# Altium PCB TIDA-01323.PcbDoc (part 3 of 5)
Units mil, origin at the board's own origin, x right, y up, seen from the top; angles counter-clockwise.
Board outline 2467 x 6135 mil, 6 copper layers (Layer 1 - Top Layer, Layer 2 - GND, Layer 3 - Sensitive, Layer 4 - GND, Layer 5 - PWR, Layer 6 - Bottom Layer), stack 62.468 mil thick; 310 components, 202 nets, 881 pads, 527 vias.
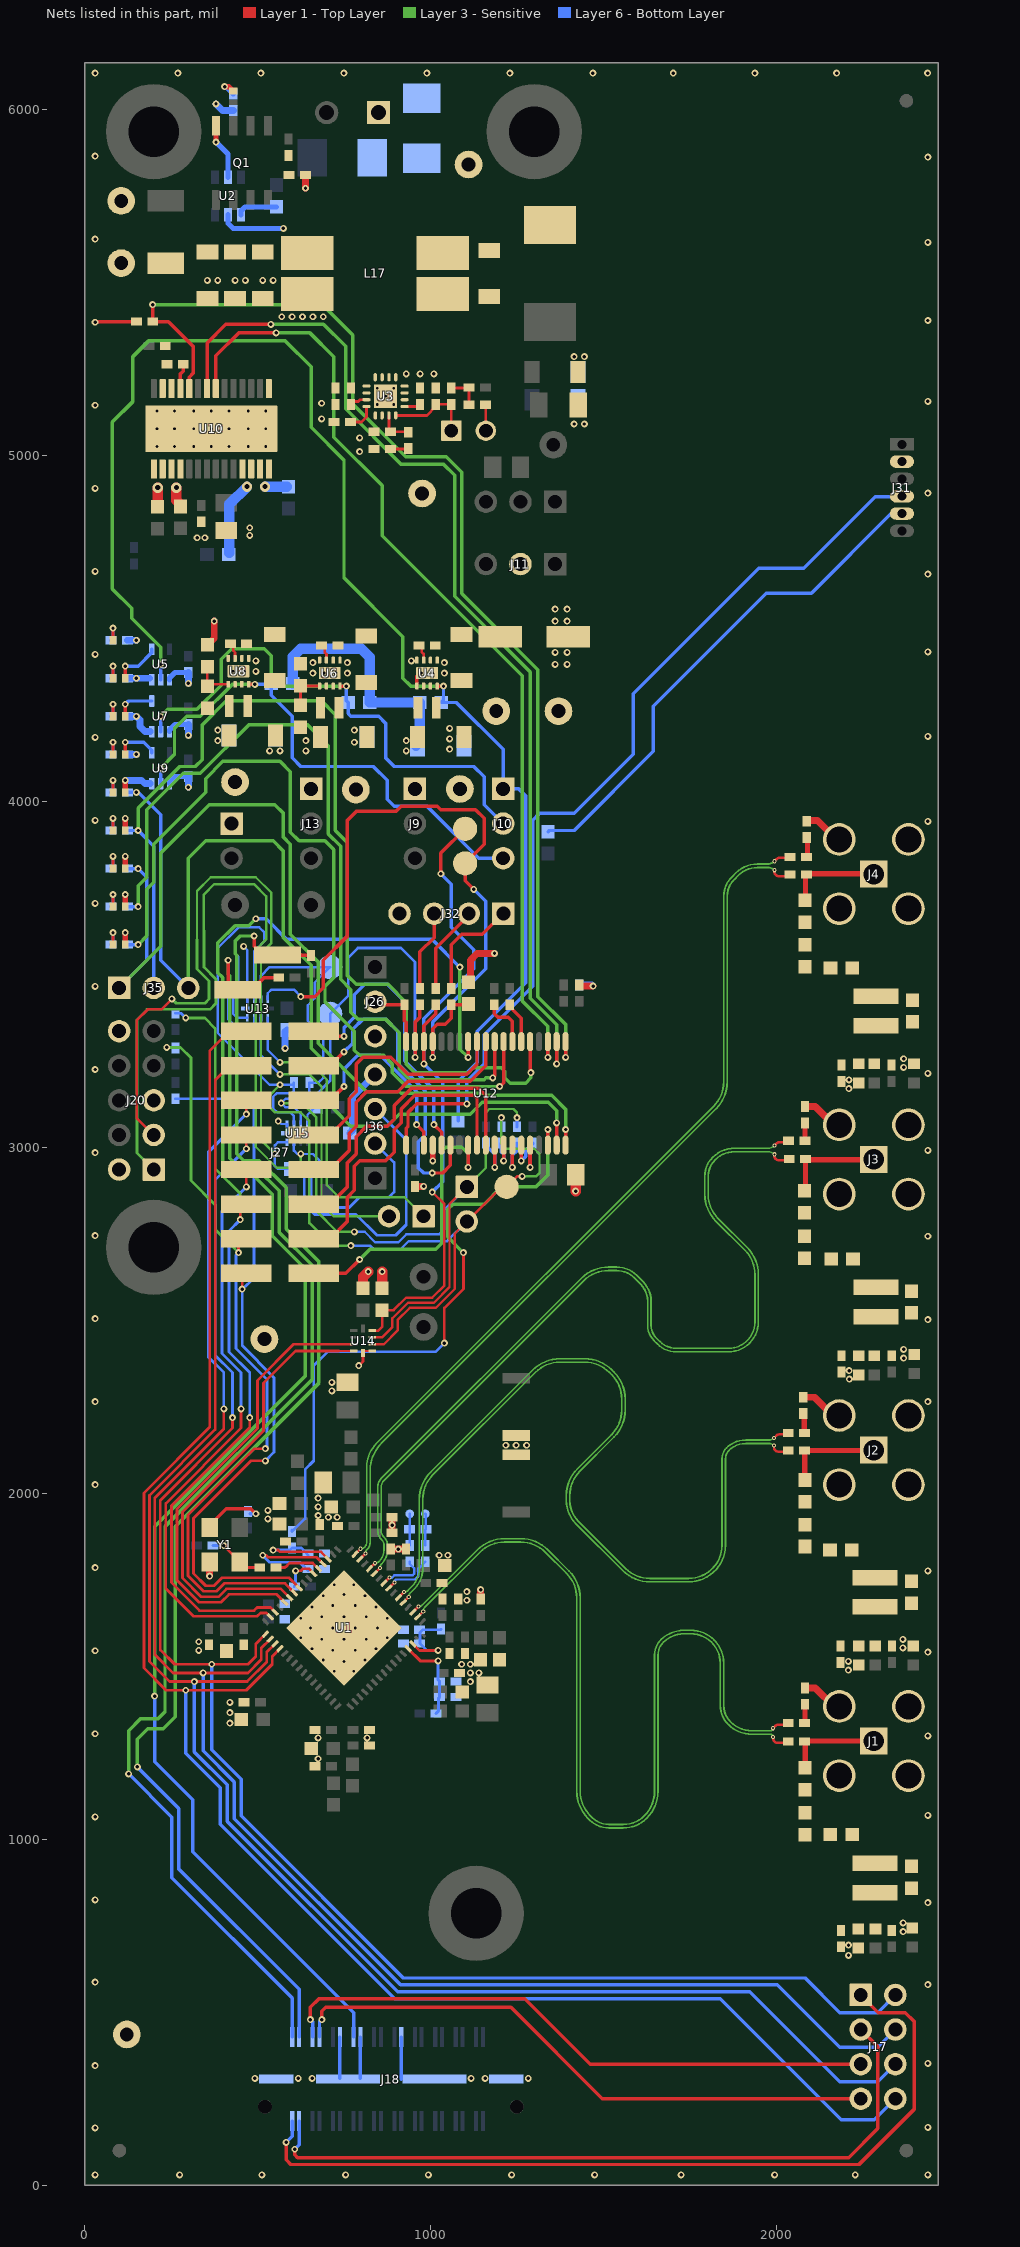
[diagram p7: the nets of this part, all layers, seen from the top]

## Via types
v1: diameter 20, hole 10, Layer 1 - Top Layer to Layer 6 - Bottom Layer, tented both sides, 397 vias
v2: diameter 19.68, hole 7.87, Layer 1 - Top Layer to Layer 6 - Bottom Layer, tented both sides, 64 vias
v3: diameter 12, hole 6, Layer 1 - Top Layer to Layer 6 - Bottom Layer, tented both sides, 58 vias
v4: diameter 30, hole 15, Layer 1 - Top Layer to Layer 6 - Bottom Layer, tented both sides, 8 vias

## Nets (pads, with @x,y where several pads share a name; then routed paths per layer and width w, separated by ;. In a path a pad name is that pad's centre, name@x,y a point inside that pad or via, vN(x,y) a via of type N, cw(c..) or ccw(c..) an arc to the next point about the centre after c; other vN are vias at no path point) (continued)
GND: C1.2 C2.2 C3.2 C4.2 C5.2 C6.2 C7.2 C8.2 C15.2 C16.2 C17.2 C18.2 C19.2 C20.2 C21.2 C22.2 C31.2 C33.2 C34.2 C35.2 C36.2 C37.2 C38.2 C39.2 C40.2 C41.2 C42.2 C43.2 C44.2 C45.2 C46.2 C47.2 C48.2 C49.2 C50.2 C51.2 C52.2 C53.2 C54.2 C55.2 C56.2 C57.2 C58.2 C59.2 C60.2 C61.2 C62.2 C63.2 C64.2 C65.2 C66.2 C67.2 C68.2 C69.2 C70.2 C71.2 C72.2 C75.2 C76.2 C77.2 C78.2 C79.2 C80.2 C81.2 C82.2 C83.2 C84.2 C85.2 C86.2 C87.2 C88.2 C89.2 C90.2 C91.2 C92.2 C93.2 C94.2 C95.2 C96.2 C97.2 C106.2 C107.2 C108.2 C109.2 C110.2 C111.2 C112.2 D3.1 D9.1 D10.1 D12.2 D13.1 D14.2 J1.MH1 J1.MH2 J1.MH3 J1.MH4 J2.MH1 J2.MH2 J2.MH3 J2.MH4 J3.MH1 J3.MH2 J3.MH3 J3.MH4 J4.MH1 J4.MH2 J4.MH3 J4.MH4 J5.1 J18.12 J18.16 J18.24 J18.MP1 J18.MP2 J18.MP3 J18.MP4 J20.2 J20.10 J26.3 J31.2 J32.4 J36.4 L17.2 R5.1 R6.1 R13.1 R14.1 R18.1 R20.1 R22.1 R25.1 R28.1 R33.2 R37.1 R38.1 R42.1 R43.1 R48.1 R51.1 R54.1 R55.1 R70.1 R71.1 R74.1 R104.1 R109.1 S1.2 S2.2 TP11.1 TP12.1 TP14.1 TP15.1 TP16.1 TP18.1 U1.65 U2.2 U3.5 U3.6 U3.10 U3.11 U3.12 U3.13 U3.14 U3.17 U4.1 U4.4 U4.5 U4.9 U5.1 U5.3 U6.1 U6.4 U6.9 U7.1 U7.3 U8.1 U8.4 U8.9 U9.1 U9.3 U10.1 U10.12 U10.13 U10.29@366,5077 U12.4 U12.15 U13.5 U13.6 U14.5 U14.6 U15.5 U15.6 Y1.2 | length 3286.9
  Layer 1 - Top Layer w7: U14.5@804.85,2411.34 U14.6@830.95,2411.34
  Layer 1 - Top Layer w8: v1(792,2369) 804.38,2381.38 U14.5@804.38,2405.44
  Layer 1 - Top Layer w10: v1@29.38,5385.87 R74.1@144.38,5386 ; U4.5@959.85,4333.47 U4.9@960,4362
  Layer 1 - Top Layer w12: v1(1287.33,2941.93) U12.15@1287.33,3006.26
  Layer 1 - Top Layer w15: D9.1@117.1,3585.87 v1(117.1,3620.87) ; D10.1@117.1,3695.87 v1(117.1,3730.87) ; D12.2@117.1,3805.87 v1(117.1,3840.87) ; D14.2@117.1,3915.87 v1(117.1,3950.87) ; D13.1@117.1,4025.87 v1(117.1,4060.87) ; v1(1005.84,2960.87) U12.4@1005.84,3006.26
  Layer 1 - Top Layer w20: R42.1@354.38,4452.37 374.38,4472.37 v1(374.38,4520.87) ; v1(361.07,1760.87) Y1.2@361.07,1800.87 ; v1(638,5772.25) C31.2@638,5810.87 ; C64.2@885,1838.87 v1(906.38,1838.87) 927.76,1838.87 C61.2@928.38,1839.49 ; C95.2@888,1885.87 888.38,1886.25 v1(888.38,1907.87) 888.38,1930.49 C92.2@888,1930.87 ; C109.2@954.38,2887.25 v1(979.38,2887.25) ; R104.1@1109.38,3477.37 1114.38,3482.37 1114.38,3540.87 1134.38,3560.87 v1(1184.38,3560.87) ; C67.2@1144.38,1694.49 v1@1144.38,1720.87 ; C111.2@1429.38,3469.49 1433,3465.87 v1(1469.38,3465.87) ; R6.1@2079.56,2277.62 2109.09,2277.62 J2.MH1@2164.28,2222.43 ; R5.1@2082,1437.62 2111.53,1437.62 J1.MH1@2166.72,1382.43 ; R13.1@2082,3117.62 2111.53,3117.62 J3.MH1@2166.72,3062.43 ; R14.1@2089,3944.62 2118.53,3944.62 J4.MH1@2173.72,3889.43
  Layer 1 - Top Layer w30: C110.2@804.38,2592.37 804.38,2625.87 v1(819.38,2640.87) ; R109.1@859.38,2592.37 v1(859.38,2640.87) ; v1(1418.88,2873.37) 1418.88,2920.37 C108.2@1419.38,2920.87
  Layer 6 - Bottom Layer w7: v1(459.38,3580.87) 469.85,3570.4 U13.6@469.85,3427.44 469.85,3400.87 U13.5@463.95,3400.87 ; v1(559.38,3075.87) 567.8,3067.44 U15.6@584.85,3067.44 U15.5@584.85,3041.34
  Layer 6 - Bottom Layer w10: J18.MP2@737.58,309.58 J18.12@737.58,428.52 ; J18.MP2@796.64,309 J18.16@796.64,428.52 ; 914.75,306.25 J18.24@914.75,428.52
  Layer 6 - Bottom Layer w15: U9.1@244.97,4051.58 244.97,4056.46 260.76,4072.25 C55.2@299.38,4072.25 ; U7.1@244.97,4201.58 244.97,4206.46 260.76,4222.25 C51.2@299.38,4222.25 ; U5.1@244.97,4351.58 244.97,4356.46 260.76,4372.25 C47.2@299.38,4372.25 ; U2.2@413.93,5695.87 413.93,5671.07 429,5656 v1(574,5656)
  Layer 6 - Bottom Layer w20: v1(117.1,4060.87) 164.38,4060.87 173.67,4051.58 U9.3@189.38,4051.58 ; R43.1@123,4135.87 v1(149.38,4135.87) ; R38.1@123,4245.87 v1(149.38,4245.87) 159.38,4235.87 159.38,4215.87 173.67,4201.58 U7.3@189.38,4201.58 ; R33.2@123,4355.87 v1(149.38,4355.87) U5.3@187.38,4355.87 ; R22.1@123,4465.87 v1(149.38,4465.87) ; v1(299.38,4040.87) C55.2@299.38,4072.25 ; v1(299.38,4190.87) C51.2@299.38,4222.25 ; v1(299.38,4340.87) C47.2@299.38,4372.25 ; v1(379.38,6015.87) 398,5997.25 R18.1@429.38,5997.25 ; v1(579.38,3285.87) 579.38,3334.37 C106.2@584.38,3339.37 ; C112.2@765.88,3040.87 774.38,3049.37 774.38,3145.87 J36.4@839.38,3210.87 ; C107.2@1429.38,3469.49 v1@1465.76,3469.49
  other v1: 30,30 274,30 512,30 754,30 993,30 1234,30 1474,30 1724,30 1994,30 2227,30 2437,30 30,166 2437,167 492,309 617,309 657,309 1117,309 1157,309 1282,309 30,346 2437,352 2437,580 30,587 2207.62,664.13 2207.62,694.13 2365.62,733.13 2365.62,758.13 2437,817 30,825 30,1065 2437,1069 674.38,1232.87 674.38,1292.87 816.38,1292.87 2437,1299 30,1305 419.38,1335.87 419.38,1365.87 419.38,1395.87 1114.38,1455.87 1114.38,1480.87 1139.38,1480.87 2207,1489 1089.38,1505.87 1114.38,1505.87 2207,1514 2437,1541 30,1545 329.38,1545.87 2365,1553 329.38,1570.87 2365,1578 1104.38,1690.87 1104.38,1715.87 1144.38,1721.87 2437,1776 30,1785 1024.38,1820.87 1049.38,1820.87 529.38,1925.87 704.38,1930.87 729.38,1930.87 674.38,1935.87 529.38,1950.87 674.38,1960.87 674.38,1985.87 30,2025 1217,2139 1247,2139 1277,2139 30,2265 2437,2265 714.38,2295.87 714.38,2320.87 2210,2330 2209.38,2354.87 2367,2391 2367,2416 2437,2502 30,2505 2437,2743 30,2745 30,2985 2437,2991 2208.62,3169.87 2209,3195 2437,3214 30,3225 2366.62,3231.13 2366.62,3256.13 30,3465 30,3705 2437,3942 30,3945 534.38,4145.87 564.38,4145.87 1054.38,4150.87 779.38,4170.87 1054.38,4180.87 30,4185 2437,4188 779.38,4205.87 1054.38,4210.87 659.38,4370.87 759.38,4370.87 1039.38,4370.87 494.38,4375.87 1359.38,4395.87 1394.38,4395.87 659.38,4400.87 759.38,4400.87 1039.38,4400.87 494.38,4405.87 944.38,4405.87 30,4425 1359.38,4430.87 1394.38,4430.87 2437,4432 1359.38,4520.87 1394.38,4520.87 1359.38,4555.87 1394.38,4555.87 2437,4657 30,4665 325,4762 347,4762 477,4769 477,4791 2437,4891 30,4905 794.38,5010.87 794.38,5050.87 1414.38,5090.87 1444.38,5090.87 684.38,5105.87 30,5145 684.38,5150.87 2437,5156 929.38,5235.87 969.38,5235.87 1009.38,5235.87 1414.38,5285.87 1444.38,5285.87 30,5385 2437,5390 569.38,5400.87 599.38,5400.87 629.38,5400.87 659.38,5400.87 689.38,5400.87 354.38,5505.87 384.38,5505.87 434.38,5505.87 464.38,5505.87 514.38,5505.87 544.38,5505.87 2437,5616 30,5625 2437,5862 30,5865 30,6105 269,6105 509,6105 749,6105 989,6105 1229,6105 1469,6105 1701,6105 1937,6105 2173,6105 2436,6105
  other v2: 721.26,1485.87 777.5,1485.87 749.38,1513.99 688.97,1518.17 809.79,1518.17 717.09,1546.28 781.67,1546.28 656.68,1550.46 842.08,1550.46 684.79,1578.58 749.38,1578.58 813.97,1578.58 624.38,1582.75 874.38,1582.75 652.5,1610.87 717.09,1610.87 781.67,1610.87 846.26,1610.87 624.38,1638.99 874.38,1638.99 684.79,1643.16 749.38,1643.16 813.97,1643.16 656.68,1671.28 842.08,1671.28 717.09,1675.46 781.67,1675.46 688.97,1703.57 809.79,1703.57 749.38,1707.75 721.26,1735.87 777.5,1735.87 692.63,4370.87 724.13,4370.87 973.63,4370.87 1005.13,4370.87 428.63,4375.87 460.13,4375.87 208.52,5025.82 259.7,5025.82 314.82,5025.82 366,5025.82 417.18,5025.82 472.3,5025.82 523.48,5025.82 208.52,5077 259.7,5077 314.82,5077 366,5077 417.18,5077 472.3,5077 523.48,5077 208.52,5128.18 259.7,5128.18 314.82,5128.18 366,5128.18 417.18,5128.18 472.3,5128.18 523.48,5128.18 845.76,5147.25 893,5147.25 869.38,5170.87 845.76,5194.49 893,5194.49
GPIO0_DES: J27.2 R56.1 U1.9 | length 2141.6
  Layer 1 - Top Layer w8: v1(455,2590) J27.2@455,2626.93 ; J27.2@462,2630.93 J27.2@466.94,2635.87 ; v1(522,2094) 480.51,2094 314.38,1927.87 314.38,1768.12 349.63,1732.87 373.68,1732.87 396.68,1755.87 590.46,1755.87 U1.9@619.93,1726.4
  Layer 6 - Bottom Layer w8: R56.1@262,3140.38 460.62,3140.38 489,3112 489,2621 v1(455,2590) 455,2428 547,2334 547,2119 v1(522,2094)
GPIO0_UC: J27.1 U12.8 | length 865.8
  Layer 1 - Top Layer w10: J27.1@661.82,2635.87 754.38,2635.87 v1(794.38,2675.87) ; v1(1108.2,2941.93) U12.8@1108.2,3006.26
  Layer 3 - Sensitive w10: v1(794.38,2675.87) 824.38,2705.87 1014.38,2705.87 1031.38,2722.87 1031.38,2989.23 1043.02,3000.87 1089.38,3000.87 1108.2,2982.05 v1(1108.2,2941.93)
GPIO1_DES: J27.4 R57.1 U1.10 | length 2212.1
  Layer 1 - Top Layer w8: v1(444.38,2695.87) 444.38,2713.31 J27.4@466.94,2735.87 ; v1(522,2129) 490.51,2129 298.38,1936.87 298.38,1761.67 343.18,1716.87 380.3,1716.87 403.3,1739.87 578.62,1739.87 U1.10@606.01,1712.48
  Layer 3 - Sensitive w8: v1(237,3289) 277,3289 307,3259 307,2904 377,2834 377,2763.25 v1(444.38,2695.87)
  Layer 6 - Bottom Layer w8: v1(237,3289) 260.62,3289 R57.1@262,3287.62 ; v1(444.38,2695.87) 437,2688.49 437,2419 527,2329 527,2134 v1(522,2129)
GPIO1_UC: J27.3 U12.9 | length 918.9
  Layer 1 - Top Layer w10: J27.3@669.38,2735.87 709.38,2735.87 759.38,2785.87 759.38,2855.87 779.38,2875.87 779.38,2945.87 794.38,2960.87 869.38,2960.87 894.38,2985.87 894.38,3050.87 914.38,3070.87 914.38,3110.87 954.38,3150.87 1124.38,3150.87 1133.79,3141.46 U12.9@1133.79,3006.26
GPIO2_DES: J27.6 R58.1 U1.14 | length 2291.9
  Layer 1 - Top Layer w8: v1(449.38,2790.87) 449.38,2818.31 J27.6@466.94,2835.87 ; v1(477,2219) 477,2190.49 250.63,1964.12 250.63,1742.07 331.83,1660.87 489.38,1660.87 498.51,1670 537.14,1670 U1.14@550.33,1656.8
  Layer 3 - Sensitive w8: v1(292,3374) 347,3374 377,3344 377,2939 449.38,2866.62 v1(449.38,2790.87)
  Layer 6 - Bottom Layer w8: R58.1@262,3387.62 278.38,3387.62 v1(292,3374) ; v1(449.38,2790.87) 417,2758.49 417,2409 477,2349 v1(477,2219)
GPIO2_UC: J27.5 U12.10 | length 882.9
  Layer 1 - Top Layer w10: J27.5@661.82,2835.87 709.38,2835.87 759.38,2885.87 759.38,2955.87 784.38,2980.87 784.38,3030.87 814.38,3060.87 874.38,3060.87 894.38,3080.87 894.38,3120.87 944.38,3170.87 1139.38,3170.87 1159.38,3150.87 U12.10@1159.38,3006.26
GPIO3_DES: J27.8 U1.15 | length 1696.9
  Layer 1 - Top Layer w8: v1(452,2244) 452,2188.49 234.38,1970.87 234.38,1724.12 313.51,1645 498.51,1645 507.63,1654.12 525.17,1654.12 U1.15@536.41,1642.88 ; v1(466.94,2885.87) J27.8@466.94,2935.87
  Layer 6 - Bottom Layer w8: v1(452,2244) 452,2349 397,2404 397,2815.93 v1(466.94,2885.87)
GPIO3_UC: J27.7 U12.29 | length 714.2
  Layer 1 - Top Layer w10: J27.7@709.38,2935.87 764.38,2990.87 764.38,3040.87 784.38,3060.87 784.38,3130.87 814.38,3160.87 904.38,3160.87 934.38,3190.87 1114.38,3190.87 1159.38,3235.87 U12.29@1159.38,3305.48
GPIO4_DES: J17.2 J27.10 U1.17 | length 4632.1
  Layer 1 - Top Layer w8: v1(427,2219) 427,2188.49 218.51,1980 218.51,1547.49 260.13,1505.87 v1(367,1505.87) 471.93,1505.87 494.38,1528.32 494.38,1564.71 U1.17@522.47,1592.8 ; v1(466.94,2995.87) J27.10@466.94,3035.87
  Layer 6 - Bottom Layer w8: v1(427,2219) 427,2349 377,2399 377,2905.93 v1(466.94,2995.87)
  Layer 6 - Bottom Layer w10: v1(367,1505.87) 367,1258.85 452,1173.85 452,1068 921,599 2082,599 2182,499 2292,499 J17.2@2343,550
GPIO4_UC: J27.9 U12.30 | length 691.8
  Layer 1 - Top Layer w10: J27.9@709.38,3035.87 764.38,3090.87 764.38,3140.87 784.38,3160.87 784.38,3240.87 804.38,3260.87 884.38,3260.87 934.38,3210.87 1104.38,3210.87 1133.79,3240.28 U12.30@1133.79,3305.48
GPIO5_DES: J17.4 J27.12 U1.18 | length 4829.2
  Layer 1 - Top Layer w8: v1(402,2244) 402,2186.49 202.63,1987.12 202.63,1533.37 255.13,1480.87 v1(342,1480.87) 471.93,1480.87 510.25,1519.19 510.25,1552.74 U1.18@536.39,1578.88 ; v1(466.94,3095.87) J27.12@466.94,3135.87
  Layer 6 - Bottom Layer w8: v1(402,2244) 402,2349 357,2394 357,2985.93 v1(466.94,3095.87)
  Layer 6 - Bottom Layer w10: v1(342,1480.87) 342,1255.57 432,1165.57 432,1059.72 912.72,579 2002,579 2182,399 2292,399 J17.4@2343,450
GPIO5_UC: J27.11 U12.3 | length 587.4
  Layer 1 - Top Layer w10: J27.11@661.82,3135.87 709.38,3135.87 v1(749.38,3175.87) ; v1(959.38,3065.87) 980.25,3045 U12.3@980.25,3006.26
  Layer 6 - Bottom Layer w10: v1(749.38,3175.87) 749.38,3225.87 789.38,3265.87 854.38,3265.87 959.38,3160.87 v1(959.38,3065.87)
GPIO6_DES: J17.6 J27.14 U1.19 | length 5022.8
  Layer 1 - Top Layer w8: J27.14@466.94,3235.87 418.87,3235.87 377,3194 377,2184.49 186.76,1994.25 186.76,1514.24 245.13,1455.87 v1(317,1455.87) 469.38,1455.87 526.13,1512.62 526.13,1540.77 U1.19@550.31,1564.95
  Layer 6 - Bottom Layer w10: v1(317,1455.87) 317,1252.28 412,1157.28 412,1051.43 904.43,559 1922,559 2182,299 2292,299 J17.6@2343,350
GPIO6_UC: J27.13 U12.6 | length 938.8
  Layer 1 - Top Layer w10: J27.13@661.82,3235.87 709.38,3235.87 v1(749.38,3275.87) ; v1(1004.38,2925.87) 1034.38,2925.87 1057.02,2948.51 U12.6@1057.02,3006.26
  Layer 6 - Bottom Layer w10: v1(749.38,3275.87) 774.38,3300.87 774.38,3340.87 804.38,3370.87 869.38,3370.87 904.38,3335.87 904.38,3242.87 984.38,3162.87 984.38,3035.87 964.38,3015.87 964.38,2940.87 979.38,2925.87 v1(1004.38,2925.87)
GPIO7_DES: J17.8 J27.16 U1.20 | length 5233.9
  Layer 1 - Top Layer w8: J27.16@466.94,3335.87 418.87,3335.87 361.13,3278.13 361.13,2191.07 170.88,2000.82 170.88,1495.12 235.13,1430.87 v1(292,1430.87) 466.93,1430.87 542,1505.94 542,1528.8 U1.20@564.24,1551.03
  Layer 6 - Bottom Layer w10: v1(292,1430.87) 292,1249 392,1149 392,1043.15 896.15,539 1837,539 2187,189 2282,189 J17.8@2343,250
GPIO7_UC: J27.15 U12.5 | length 863.3
  Layer 1 - Top Layer w10: J27.15@661.82,3335.87 676.82,3320.87 v1(749.38,3320.87) ; v1(1009.38,3065.87) 1031.43,3043.82 U12.5@1031.43,3006.26
  Layer 6 - Bottom Layer w10: v1(749.38,3320.87) 749.38,3345.87 779.38,3375.87 779.38,3440.87 809.38,3470.87 874.38,3470.87 924.38,3420.87 924.38,3250.87 1009.38,3165.87 v1(1009.38,3065.87)
I2C_SCL_DES: U1.12 U14.3 | length 1353.2
  Layer 1 - Top Layer w7: 737,2431.03 U14.3@777.8,2431.03
  Layer 1 - Top Layer w8: U1.12@578.17,1684.64 554.82,1708 416.51,1708 393.51,1685 330.15,1685 266.51,1748.64 266.51,1955 499.32,2187.81 499.32,2326.32 604.03,2431.03 737,2431.03
I2C_SCL_EXT: J20.1 J36.2 R116.1 U15.3 | length 2859.8
  Layer 3 - Sensitive w7: 344.38,3625.87 344.38,3730.87 374.38,3760.87 489.38,3760.87 524.38,3725.87 524.38,3600.87 494.38,3570.87 494.38,3001.62 555.13,2940.87 604.38,2940.87 624.38,2960.87 v1(624.38,2980.87)
  Layer 3 - Sensitive w8: J20.1@199.38,2935.87 151,2984.25 151,3369.87 180.13,3399 362,3399 379.38,3416.38 379.38,3485.87 344.38,3520.87 344.38,3625.87
  Layer 6 - Bottom Layer w7: U15.3@604.54,3014.29 604.54,2990.71 614.38,2980.87 v1(624.38,2980.87) 659.38,2980.87 699.38,2940.87 R116.1@699.38,2937.37
  Layer 6 - Bottom Layer w8: R116.1@699.38,2937.37 665.88,2937.37 654.38,2925.87 654.38,2845.87 674.38,2825.87 764.38,2825.87 794.38,2855.87 879.38,2855.87 894.38,2870.87 894.38,2955.87 J36.2@839.38,3010.87
I2C_SCL_SOC: J18.2 J28.1 R95.1 U13.3 | length 4209.2
  Layer 1 - Top Layer w10: v1(414.38,3540.87) 414.38,3455.87 J28.1@441.9,3455.87 484.38,3455.87 519.38,3490.87 R95.1@560.76,3490.87
  Layer 3 - Sensitive w10: v1(127,1189) 127,1314 162,1349 212,1349 232,1369 232,1904 657,2329 657,2659 562,2754 562,2874 497,2939 449.38,2939 419.38,2969 419.38,3495.87 415,3500.42 414.38,3501.04 v1(414.38,3540.87)
  Layer 6 - Bottom Layer w7: v1(414.38,3540.87) 414.38,3370.87 439.38,3345.87 479.38,3345.87 489.54,3356.03 U13.3@489.54,3374.29
  Layer 6 - Bottom Layer w10: v1(127,1189) 252,1064 252,889 599.79,541.21 J18.2@599.79,428.52
I2C_SCL_UC: J29.1 R93.1 R99.1 TP26.1 U13.8 U14.8 U15.8 | length 2856.5
  Layer 1 - Top Layer w7: U14.8@830.95,2450.71 859.22,2450.71 889.38,2480.87 889.38,2505.87 934.38,2550.87 1009.38,2550.87 1054.38,2595.87 1054.38,2835.87 J29.1@1104.38,2885.87
  Layer 3 - Sensitive w7: v1(568,3128) 627.25,3128 669.38,3085.87 669.38,2815.87 729.38,2755.87 v1(779.38,2755.87) ; J29.1@1104.38,2885.87 1159.38,2940.87 1159.38,3100.87 1169.38,3110.87 1239.38,3110.87 1249.38,3100.87 v1(1249.38,3085.87)
  Layer 6 - Bottom Layer w7: U13.8@509.22,3427.44 509.22,3495.71 534.38,3520.87 TP26.1@709.38,3520.87 664.38,3475.87 664.38,3430.87 644.38,3410.87 644.38,3365.87 689.38,3320.87 689.38,3200.87 675.76,3187.25 R93.1@649.38,3187.25 649.38,3160.87 629.38,3140.87 580.87,3140.87 v1(568,3128) 580.13,3115.87 604.38,3115.87 624.22,3096.03 U15.8@624.22,3067.44 ; v1(779.38,2755.87) 809.38,2755.87 839.38,2725.87 906.49,2725.87 929.62,2749 1024.38,2749 1039.38,2764 1039.38,2820.87 J29.1@1104.38,2885.87
  Layer 6 - Bottom Layer w10: R99.1@1249.38,3059.49 v1(1249.38,3085.87)
I2C_SDA_DES: U1.11 U14.4 | length 1312.3
  Layer 1 - Top Layer w7: 733.91,2411.34 U14.4@777.8,2411.34
  Layer 1 - Top Layer w8: U1.11@592.09,1698.56 566.78,1723.87 409.93,1723.87 386.93,1700.87 336.73,1700.87 282.38,1755.22 282.38,1945.87 517,2180.49 517,2319 609.34,2411.34 733.91,2411.34
I2C_SDA_EXT: J20.3 J36.3 R114.1 U15.4 | length 2956.4
  Layer 1 - Top Layer w8: J20.3@199.38,3035.87 150,3085.25 150,3367 182,3399 222,3399 v1(252,3429)
  Layer 3 - Sensitive w7: 324.38,3600.87 324.38,3740.87 364.38,3780.87 494.38,3780.87 539.38,3735.87 539.38,3590.87 509.38,3560.87 509.38,3020.87 v1(549.38,2980.87)
  Layer 3 - Sensitive w8: v1(252,3429) 264.38,3416.62 347,3416.62 359.38,3429 359.38,3480.87 324.38,3515.87 324.38,3600.87
  Layer 6 - Bottom Layer w7: U15.4@584.85,3014.29 557.8,3014.29 549.38,3005.87 v1(549.38,2980.87) 549.38,2945.87 557.88,2937.37 R114.1@594.38,2937.37
  Layer 6 - Bottom Layer w8: R114.1@594.38,2937.37 622.88,2937.37 634.38,2925.87 634.38,2835.87 664.38,2805.87 784.38,2805.87 844.38,2745.87 898.87,2745.87 929.38,2776.38 929.38,3020.87 J36.3@839.38,3110.87
I2C_SDA_SOC: J18.4 J28.2 R96.1 U13.4 | length 4325.6
  Layer 1 - Top Layer w10: v1(489.38,3610.87) 489.38,3580.87 514.38,3555.87 J28.2@556.86,3555.87 653,3555.87 R96.1@654.38,3554.49
  Layer 3 - Sensitive w10: v1(152,1209) 152,1289 182,1319 227,1319 262,1354 262,1904 677,2319 677,2669 582,2764 582,2884 504.5,2961.5 459.5,2961.5 439.38,2981.62 439.38,3555.62 434.38,3560.62 434.38,3595.87 449.38,3610.87 v1(489.38,3610.87)
  Layer 6 - Bottom Layer w7: U13.4@469.85,3374.29 440.95,3374.29 429.38,3385.87 429.38,3430.87 444.38,3445.87 444.38,3550.87 434.38,3560.87 434.38,3595.87 449.38,3610.87 v1(489.38,3610.87)
  Layer 6 - Bottom Layer w10: v1(152,1209) 272,1089 272,914 619.47,566.53 J18.4@619.47,428.52
I2C_SDA_UC: J29.2 R94.1 R98.1 TP27.1 U13.7 U14.7 U15.7 | length 3214.5
  Layer 1 - Top Layer w7: U14.7@830.95,2431.03 864.54,2431.03 904.38,2470.87 904.38,2500.87 939.38,2535.87 1014.38,2535.87 1069.38,2590.87 1069.38,2750.87 J29.2@1104.38,2785.87 1204.38,2885.87 TP27.1@1219.38,2885.87 1249.38,2915.87 v1(1264.38,2915.87)
  Layer 3 - Sensitive w7: v1(564.38,3180.87) 529.38,3145.87 529.38,3120.87 549.38,3100.87 624.38,3100.87 649.38,3075.87 649.38,2780.87 714.38,2715.87 v1(769.38,2715.87) ; v1(1204.38,3085.87) 1204.38,3010.87 1219.38,2995.87 1299.38,2995.87 1314.38,2980.87 1314.38,2925.87 1304.38,2915.87 v1(1264.38,2915.87)
  Layer 6 - Bottom Layer w7: U13.7@489.54,3427.44 489.54,3566.03 519.38,3595.87 519.38,3620.87 504.38,3635.87 444.38,3635.87 384.38,3575.87 384.38,3330.87 534.38,3180.87 v1(564.38,3180.87) R94.1@598,3180.87 ; 604.38,3090.87 594.38,3100.87 557.13,3100.87 545,3113 545,3146.49 554.38,3155.87 597.38,3155.87 604.38,3162.87 R94.1@604.38,3187.25 ; U15.7@604.54,3067.44 604.54,3090.87 ; v1(769.38,2715.87) 824.38,2715.87 834.38,2705.87 913.36,2705.87 936.49,2729 1047.51,2729 J29.2@1104.38,2785.87 ; R98.1@1204.38,3059.49 v1(1204.38,3085.87)
I2C_SW_DES: R107.1 R109.2 TP28.1 U12.36 U14.9 | length 1973.5
  Layer 1 - Top Layer w7: U14.9@830.95,2470.4 848.91,2470.4 859.38,2480.87 R109.2@859.38,2529.37 892.88,2529.37 929.38,2565.87 1004.38,2565.87 1039.38,2600.87 1039.38,2835.87 v1(1004.38,2870.87)
  Layer 1 - Top Layer w10: v1(980.25,3241.14) U12.36@980.25,3305.48 980.25,3351.74 1014.38,3385.87 R107.1@1014.38,3412.25 ; v1(1029.38,3790.87) 1029.38,3850.87 TP28.1@1099.38,3920.87
  Layer 6 - Bottom Layer w10: v1(1004.38,2870.87) 1034.38,2900.87 1034.38,3187.01 v1(980.25,3241.14) 980.25,3371.74 1124.38,3515.87 1124.38,3570.87 1059.38,3635.87 1059.38,3760.87 v1(1029.38,3790.87)
I2C_SW_EXTERNAL: R108.1 R113.1 TP29.1 U12.37 U15.9 | length 1185.7
  Layer 1 - Top Layer w10: v1(954.65,3260.08) U12.37@954.65,3305.48 954.65,3361.15 968.88,3375.37 R108.1@968.88,3412.25
  Layer 6 - Bottom Layer w7: U15.9@643.91,3067.44 643.91,3094.4 665.38,3115.87 R113.1@667.88,3115.87
  Layer 6 - Bottom Layer w8: R113.1@667.88,3115.87 667.88,3150.87 709.38,3192.37 TP29.1@709.38,3385.87 761.88,3438.37 761.88,3548.37 789.38,3575.87 914.38,3575.87 954.65,3535.59 v1(954.65,3260.08)
I2C_SW_SOC: R104.2 R105.1 TP25.1 U12.35 U13.9 | length 2184.4
  Layer 1 - Top Layer w10: v1(624.38,3435.87) 664.38,3435.87 689.38,3460.87 689.38,3540.87 759.38,3610.87 759.38,3945.87 784.38,3970.87 899.38,3970.87 914.38,3985.87 1019.38,3985.87 1029.38,3975.87 1129.38,3975.87 1154.38,3950.87 1154.38,3875.87 TP25.1@1099.38,3820.87 1099.38,3770.87 v1(1124.38,3745.87) ; v1(1005.84,3260.08) U12.35@1005.84,3305.48 1005.84,3342.33 1019.38,3355.87 1042.02,3355.87 1059.38,3373.23 R105.1@1059.38,3412.25 1101.51,3412.25 R104.2@1109.38,3404.37
  Layer 6 - Bottom Layer w7: U13.9@528.91,3427.44 528.91,3445.4 539.38,3455.87 604.38,3455.87 v1(624.38,3435.87)
  Layer 6 - Bottom Layer w10: v1(1005.84,3260.08) 1005.84,3362.33 1159.38,3515.87 1159.38,3710.87 v1(1124.38,3745.87)
IDX: C70.1 R47.1 R48.2 U1.46 | length 236.7
  Layer 1 - Top Layer w8: U1.46@948.43,1564.94 967.49,1545.87 v1(1021.38,1545.87)
  Layer 6 - Bottom Layer w8: v1(1021.38,1545.87) 989.38,1545.87 969.38,1565.87 969.38,1597.25 978,1605.87 1028,1605.87 R47.1@1029.38,1607.25
LED_BLUE: R59.2 U12.28 | length 2431.3
  Layer 1 - Top Layer w10: v1(1179.38,3200.87) 1184.97,3206.46 U12.28@1184.97,3305.48
  Layer 3 - Sensitive w10: v1(154.38,3695.87) 154.38,3755.87 179.38,3780.87 179.38,3975.87 284.38,4080.87 334.38,4080.87 474.38,4220.87 644.38,4220.87 704.38,4160.87 704.38,3905.87 739.38,3870.87 739.38,3485.87 769.38,3455.87 769.38,3390.87 789.38,3370.87 869.38,3370.87 909.38,3330.87 909.38,3225.87 939.38,3195.87 1154.38,3195.87 1159.38,3200.87 v1(1179.38,3200.87)
  Layer 6 - Bottom Layer w10: R59.2@123,3695.87 v1(154.38,3695.87)
LED_GREEN: J35.3 R115.2 U12.18 | length 2949.2
  Layer 1 - Top Layer w10: U12.18@1364.1,3006.26 v1(1364.1,3070.59)
  Layer 3 - Sensitive w10: J35.3@299.38,3460.87 299.38,3835.87 349.38,3885.87 544.38,3885.87 574.38,3855.87 574.38,3605.87 654.38,3525.87 654.38,3285.87 719.38,3220.87 719.38,3110.87 769.38,3060.87 874.38,3060.87 909.38,3095.87 1114.38,3095.87 1149.38,3130.87 1339.38,3130.87 1364.1,3106.14 v1(1364.1,3070.59)
  Layer 6 - Bottom Layer w10: R115.2@123,4025.87 v1(149.38,4025.87) 154.38,4025.87 219.38,3960.87 219.38,3540.87 J35.3@299.38,3460.87
LED_ORANGE: J35.2 R117.2 U12.24 | length 3010.1
  Layer 1 - Top Layer w10: U12.24@1287.33,3305.48 1287.33,3217.92 v1(1289.38,3215.87)
  Layer 3 - Sensitive w10: v1(154.38,3915.87) 154.38,3980.87 274.38,4100.87 319.38,4100.87 339.38,4120.87 339.38,4220.87 409.38,4290.87 684.38,4290.87 724.38,4250.87 724.38,3915.87 759.38,3880.87 759.38,3495.87 784.38,3470.87 877.07,3470.87 929.38,3418.56 929.38,3240.87 954.38,3215.87 1109.38,3215.87 1123.51,3230 1204.38,3230 1214.38,3220 1214.38,3200.87 1229.38,3185.87 1274.38,3185.87 1289.38,3200.87 v1(1289.38,3215.87)
  Layer 6 - Bottom Layer w10: R117.2@123,3915.87 v1(154.38,3915.87) 199.38,3870.87 J35.2@199.38,3460.87
LED_PINK: R111.2 U12.27 | length 2428.9
  Layer 1 - Top Layer w10: v1(1199.38,3175.87) 1210.56,3187.05 U12.27@1210.56,3305.48
  Layer 3 - Sensitive w10: v1(154.38,3585.87) 179.38,3610.87 179.38,3745.87 199.38,3765.87 199.38,3875.87 349.38,4025.87 349.38,4065.87 399.38,4115.87 564.38,4115.87 594.38,4085.87 594.38,3910.87 619.38,3885.87 694.38,3885.87 719.38,3860.87 719.38,3490.87 694.38,3465.87 694.38,3420.87 779.38,3335.87 779.38,3280.87 794.38,3265.87 864.38,3265.87 889.38,3240.87 889.38,3215.87 929.38,3175.87 v1(1199.38,3175.87)
  Layer 6 - Bottom Layer w10: R111.2@123,3585.87 v1(154.38,3585.87)
LED_YELLOW: J35.1 R112.2 U12.19 | length 2887.8
  Layer 1 - Top Layer w10: U12.19@1389.69,3006.26 v1(1389.69,3051.66)
  Layer 3 - Sensitive w10: J35.1@99.38,3460.87 219.38,3580.87 219.38,3850.87 359.38,3990.87 549.38,3990.87 574.38,3965.87 574.38,3895.87 594.38,3875.87 594.38,3615.87 674.38,3535.87 674.38,3300.87 814.38,3160.87 909.38,3160.87 914.38,3155.87 1154.38,3155.87 1159.38,3150.87 1349.38,3150.87 1389.69,3110.55 v1(1389.69,3051.66)
  Layer 6 - Bottom Layer w10: J35.1@99.38,3460.87 179.38,3540.87 179.38,3780.87 v1(154.38,3805.87) R112.2@123,3805.87
LOCAL_1V1: C53.1 C54.1 J15.1 L20.2 R40.2 TP10.1 U8.6
  other v1: 384.38,4175.87 384.38,4205.87
LOCAL_1V8: C49.1 C50.1 J13.1 L19.2 R35.2 TP9.1 U6.6
  other v1: 639.38,4145.87 639.38,4175.87
LOCAL_3V3: C44.1 C45.1 J9.1 L18.2 R29.2 R34.1 R39.1 TP8.1 U4.6 | length 722.8
  Layer 6 - Bottom Layer w30: R39.1@601.64,4340.87 601.64,4418.13 624.38,4440.87 799.38,4440.87 824.11,4416.14 R34.1@824.11,4285.87 R29.2@967.88,4285.87 967.88,4171.3 C45.1@957.45,4160.87
  other v1: 929.38,4145.87 929.38,4175.87
LPTX_N: C74.1 U1.57 | length 138.7
  Layer 1 - Top Layer w7: U1.57@864.91,1740.32 v3(880.9,1756.3)
  Layer 6 - Bottom Layer w7: v3(880.9,1756.3) 887.84,1756.3 894.41,1762.87 947.38,1762.87 952.38,1767.87 952.38,1782.87 939.38,1795.87 C74.1@939.38,1802.32
LPTX_P: C73.1 U1.56 | length 151.9
  Layer 1 - Top Layer w7: U1.56@878.83,1726.4 v3(894.82,1742.38)
  Layer 6 - Bottom Layer w7: v3(894.82,1742.38) 894.82,1746.31 899.38,1750.87 954.38,1750.87 964.38,1760.87 964.38,1781.87 984.38,1801.87 C73.1@984.38,1802.32
MODE: C77.1 R53.1 R55.2 U1.45 | length 259.3
  Layer 1 - Top Layer w9: U1.45@934.51,1551.02 969.65,1515.87 v1(1021.38,1515.87)
  Layer 6 - Bottom Layer w9: R53.1@1015.62,1364 1022,1370.38 1022,1407.11 R55.2@1025.76,1410.87 C77.1@1025.76,1455.87 1021.38,1460.25 v1(1021.38,1515.87)
MODE_UC: J26.2 R91.1 U12.38 | length 194
  Layer 1 - Top Layer w10: J26.2@839.38,3410.87 840.76,3412.25 R91.1@923.88,3412.25 923.88,3366.37 929.06,3361.18 U12.38@929.06,3305.48
NetC1_1: C1.1 C2.1 L1.2 L4.2 R2.2
NetC5_1: C5.1 C6.1 L2.2 L6.2 R4.2
NetC9_1: C9.1 J1.1 L7.1 | length 283.4
  Layer 1 - Top Layer w15: C9.1@2080.62,1282.99 2081.63,1284 J1.1@2290.14,1284 ; L7.1@2082.62,1209 C9.1@2082.62,1282.5
NetC10_1: C10.1 J2.1 L8.1 | length 274.9
  Layer 1 - Top Layer w15: C10.1@2080.62,2124 J2.1@2282,2124 ; L8.1@2081,2045.37 C10.1@2081,2118.87
NetC11_1: C11.1 R5.2 | length 54.9
  Layer 1 - Top Layer w15: C11.1@2080.62,1336 2082,1337.38 R5.2@2082,1390.38
NetC12_1: C12.1 R6.2 | length 53
  Layer 1 - Top Layer w15: C12.1@2079.56,2177.38 R6.2@2079.56,2230.38
NetC15_1: C15.1 C16.1 L9.2 L12.2 R10.2
NetC19_1: C19.1 C20.1 L10.2 L14.2 R12.2
NetC23_1: C23.1 J3.1 L15.1 | length 290.4
  Layer 1 - Top Layer w15: L15.1@2083.56,2874.5 C23.1@2083.56,2966 ; C23.1@2085.56,2964 J3.1@2284.44,2964
NetC24_1: C24.1 J4.1 L16.1 | length 270.9
  Layer 1 - Top Layer w15: L16.1@2083.74,3714 C24.1@2083.74,3787.5 ; C24.1@2094,3791 J4.1@2291.44,3791
NetC25_1: C25.1 R13.2 | length 53
  Layer 1 - Top Layer w15: C25.1@2082,3017.38 R13.2@2082,3070.38
NetC26_1: C26.1 R14.2 | length 53
  Layer 1 - Top Layer w15: C26.1@2089,3844.38 R14.2@2089,3897.38
NetC29_2: C29.2 C31.1
NetC30_2: C30.2 U2.1 | length 117.8
  Layer 6 - Bottom Layer w15: U2.1@451.33,5695.87 451.33,5706.33 463.5,5718.5 C30.2@553.67,5718.5
NetC32_1: C32.1 D4.2 L17.4
NetC32_2: C32.2 L17.3 U3.1 U3.15 U3.16
NetC36_1: C36.1 C37.1 C38.1 C39.1 L17.1 R17.2 R21.1 TP5.1 U3.2
NetC40_1: C40.1 U3.4 | length 82.8
  Layer 1 - Top Layer w8: C40.1@768,5096.36 799.87,5096.36 814.26,5110.75 U3.4@814.26,5141.34
NetC41_1: C41.1 R23.2 U3.7 | length 101.2
  Layer 1 - Top Layer w8: U3.7@879.22,5115.75 879.22,5072.99 C41.1@883.83,5068.37 933.83,5068.37 R23.2@935.21,5067
NetC42_1: C42.1 R23.1 | length 51.9
  Layer 1 - Top Layer w8: C42.1@883.83,5018.37 933.83,5018.37 R23.1@935.21,5019.75
NetC43_1: C43.1 C46.1 C48.1 C52.1 J11.2 R31.2 R36.2 R41.2 TP7.1 U4.2 U6.2 U8.2
NetC73_2: C73.2 R50.2 TP19.1 | length 92.6
  Layer 6 - Bottom Layer w7: C73.2@984.38,1849.57 984.38,1894.32 R50.2@986,1895.95 986,1939.25 TP19.1@984.38,1940.87
NetC74_2: C74.2 R50.1 TP20.1 | length 91.3
  Layer 6 - Bottom Layer w7: C74.2@939.38,1849.57 TP20.1@939.38,1940.87
NetD1_2: D1.2 D3.2
NetD2_2: D2.2 R18.2 | length 63.9
  Layer 1 - Top Layer w15: v1(404.38,6065.87) 417.1,6065.87 D2.2@429.38,6053.59
  Layer 6 - Bottom Layer w15: v1(404.38,6065.87) 408,6065.87 R18.2@429.38,6044.49
NetD5_1: D5.1 R22.2 | length 72.4
  Layer 1 - Top Layer w10: D5.1@81.66,4465.87 v1(81.66,4500.87)
  Layer 6 - Bottom Layer w10: R22.2@75.76,4465.87 81.66,4471.77 v1(81.66,4500.87)
NetD6_1: D6.1 U5.4 | length 137.9
  Layer 1 - Top Layer w10: D6.1@117.1,4355.87 v1(117.1,4390.87)
  Layer 6 - Bottom Layer w10: v1(117.1,4390.87) 154.38,4390.87 193.79,4430.28 U5.4@193.79,4440.16
NetD6_2: D6.2 R33.1 | length 72.4
  Layer 1 - Top Layer w10: D6.2@81.66,4355.87 v1(81.66,4390.87)
  Layer 6 - Bottom Layer w10: R33.1@75.76,4355.87 81.66,4361.77 v1(81.66,4390.87)
NetD7_1: D7.1 U7.4 | length 115.5
  Layer 1 - Top Layer w10: D7.1@117.1,4245.87 v1(117.1,4280.87)
  Layer 6 - Bottom Layer w10: v1(117.1,4280.87) 126.39,4290.16 U7.4@193.79,4290.16
NetD7_2: D7.2 R38.2 | length 72.4
  Layer 1 - Top Layer w10: D7.2@81.66,4245.87 v1(81.66,4280.87)
  Layer 6 - Bottom Layer w10: R38.2@75.76,4245.87 81.66,4251.78 v1(81.66,4280.87)
NetD8_1: D8.1 R43.2 | length 72.4
  Layer 1 - Top Layer w10: D8.1@81.66,4135.87 v1(81.66,4170.87)
  Layer 6 - Bottom Layer w10: R43.2@75.76,4135.87 81.66,4141.77 v1(81.66,4170.87)
NetD8_2: D8.2 U9.4 | length 128.6
  Layer 1 - Top Layer w10: D8.2@117.1,4135.87 v1(117.1,4170.87)
  Layer 6 - Bottom Layer w10: v1(117.1,4170.87) 170.25,4170.87 193.79,4147.33 U9.4@193.79,4140.16
NetD9_2: D9.2 R111.1 | length 72.4
  Layer 1 - Top Layer w10: D9.2@81.66,3585.87 v1(81.66,3620.87)
  Layer 6 - Bottom Layer w10: R111.1@75.76,3585.87 81.66,3591.78 v1(81.66,3620.87)
NetD10_2: D10.2 R59.1 | length 72.4
  Layer 1 - Top Layer w10: D10.2@81.66,3695.87 v1(81.66,3730.87)
  Layer 6 - Bottom Layer w10: R59.1@75.76,3695.87 81.66,3701.78 v1(81.66,3730.87)
NetD12_1: D12.1 R112.1 | length 72.4
  Layer 1 - Top Layer w10: D12.1@81.66,3805.87 v1(81.66,3840.87)
  Layer 6 - Bottom Layer w10: R112.1@75.76,3805.87 81.66,3811.78 v1(81.66,3840.87)
NetD13_2: D13.2 R115.1 | length 72.4
  Layer 1 - Top Layer w10: D13.2@81.66,4025.87 v1(81.66,4060.87)
  Layer 6 - Bottom Layer w10: R115.1@75.76,4025.87 81.66,4031.77 v1(81.66,4060.87)
NetD14_1: D14.1 R117.1 | length 72.4
  Layer 1 - Top Layer w10: D14.1@81.66,3915.87 v1(81.66,3950.87)
  Layer 6 - Bottom Layer w10: R117.1@75.76,3915.87 81.66,3921.77 v1(81.66,3950.87)
NetJ8_1: J8.1 R27.1 R28.2 U3.8 | length 254.1
  Layer 1 - Top Layer w8: U3.8@898.91,5115.75 989.26,5115.75 1014.38,5140.87 R28.2@1014.38,5147.74 R27.1@1059.38,5147.74 J8.1@1059.38,5071.36
NetJ8_2: J8.2 R26.1 | length 75.6
  Layer 1 - Top Layer w8: R26.1@1158,5146.36 1159.38,5144.98 J8.2@1159.38,5071.36
NetJ17_1: J17.1 J18.1 | length 2446.1
  Layer 1 - Top Layer w10: v1(582,124) 582,74 596,60 2238,60 2397,219 2397,474 2372,499 2294,499 J17.1@2243,550
  Layer 6 - Bottom Layer w10: v1(582,124) 599.79,141.79 J18.1@599.79,185.61
NetJ17_3: J17.3 J18.3 | length 2132.2
  Layer 1 - Top Layer w10: v1(607,104) 607,88 615,80 2208,80 2292,164 2292,401 J17.3@2243,450
  Layer 6 - Bottom Layer w10: v1(607,104) 619.47,116.47 J18.3@619.47,185.61
NetJ17_5: J17.5 J18.6 | length 1768
  Layer 1 - Top Layer w10: v1(652,479) 652,514 677,539 1272,539 1461,350 J17.5@2243,350
  Layer 6 - Bottom Layer w10: v1(652,479) 658.84,472.16 J18.6@658.84,428.52
NetJ17_7: J17.7 J18.8 | length 1748.5
  Layer 1 - Top Layer w10: v1(685.37,479) 685.37,502.37 697,514 1232,514 1496,250 J17.7@2243,250
  Layer 6 - Bottom Layer w10: J18.8@678.53,428.52 678.53,472.16 v1(685.37,479)
NetJ30_1: J30.1 U13.1 | length 921.1
  Layer 3 - Sensitive w7: v1(564.38,3245.87) 649.38,3245.87 699.38,3195.87 699.38,2890.87 734.38,2855.87 924.38,2855.87 J30.1@979.38,2800.87
  Layer 6 - Bottom Layer w7: U13.1@528.91,3374.29 528.91,3281.34 v1(564.38,3245.87)
NetJ30_2: J30.2 U13.2 | length 870.3
  Layer 3 - Sensitive w7: v1(564.38,3210.87) 649.38,3210.87 684.38,3175.87 684.38,2835.87 719.38,2800.87 J30.2@879.38,2800.87
  Layer 6 - Bottom Layer w7: U13.2@509.22,3374.29 509.22,3266.03 v1(564.38,3210.87)
NetJ31_5: J31.5 R106.1 | length 1484.9
  Layer 6 - Bottom Layer w10: R106.1@1339.38,3912.37 1342.88,3915.87 1414.38,3915.87 1643.13,4144.62 1643.13,4275.13 1970.12,4602.12 2100.63,4602.12 2329.38,4830.87 J31.5@2367.38,4830.87
NetJ32_1: J32.1 R105.2 | length 314
  Layer 1 - Top Layer w10: R105.2@1059.38,3459.49 1059.38,3585.87 1089.38,3615.87 1149.38,3615.87 1209.1,3675.59 J32.1@1209.88,3675.59
NetJ32_2: J32.2 R107.2 | length 255.7
  Layer 1 - Top Layer w10: R107.2@1014.38,3459.49 1014.38,3575.87 1109.88,3671.37 J32.2@1109.88,3675.59
NetJ32_3: J32.3 R108.2 | length 233.1
  Layer 1 - Top Layer w10: R108.2@968.88,3459.49 968.88,3565.37 1009.88,3606.37 J32.3@1009.88,3675.59
NetL3_1: L3.1 L7.2
NetL3_2: L3.2 L27.1
NetL4_1: L4.1 L27.2 R2.1
NetL5_1: L5.1 L8.2
NetL5_2: L5.2 L28.1
NetL6_1: L6.1 L28.2 R4.1
NetL11_1: L11.1 L15.2
NetL11_2: L11.2 L29.1
NetL12_1: L12.1 L29.2 R10.1
NetL13_1: L13.1 L16.2
NetL13_2: L13.2 L30.1
NetL14_1: L14.1 L30.2 R12.1
NetL18_1: L18.1 U4.7
NetL19_1: L19.1 U6.7
NetL20_1: L20.1 U8.7
NetQ1_4: Q1.4 U2.5 | length 163.3
  Layer 1 - Top Layer w15: v1(379.38,5905.87) Q1.4@379.38,5953.15
  Layer 6 - Bottom Layer w15: v1(379.38,5905.87) 413.93,5871.32 U2.5@413.93,5804.13
NetR21_2: R21.2 U3.3 | length 50.6
  Layer 1 - Top Layer w8: R21.2@769.38,5147.25 778,5155.87 790.38,5155.87 795.54,5161.03 U3.3@814.26,5161.03
NetR24_2: R24.2 R26.2 R27.2 | length 101.9
  Layer 1 - Top Layer w8: R27.2@1059.38,5194.98 1109.38,5194.98 R24.2@1110.76,5196.36 R26.2@1110.76,5146.36
NetR25_2: R25.2 U3.9 | length 47.5
  Layer 1 - Top Layer w8: U3.9@924.5,5141.34 962.98,5141.34 R25.2@969.38,5147.74
NetR31_1: R31.1 U4.3 | length 48.3
  Layer 1 - Top Layer w8: R31.1@965.76,4450.87 974.38,4442.25 974.38,4430.87 979.54,4425.71 U4.3@979.54,4408.27
NetR35_1: R35.1 R37.2 U6.5 | length 111
  Layer 1 - Top Layer w8: R35.1@623.38,4277.37 623.38,4332.56 624.28,4333.47 U6.5@678.85,4333.47
NetR36_1: R36.1 U6.3 | length 48.3
  Layer 1 - Top Layer w8: R36.1@684.76,4450.87 693.38,4442.25 693.38,4430.87 698.54,4425.71 U6.3@698.54,4408.27
NetR40_1: R40.1 R42.2 U8.5 | length 120
  Layer 1 - Top Layer w8: R42.2@354.38,4389.37 R40.1@354.38,4332.37 360.48,4338.47 U8.5@414.85,4338.47
NetR41_1: R41.1 U8.3 | length 48.3
  Layer 1 - Top Layer w8: R41.1@420.76,4455.87 429.38,4447.25 429.38,4435.87 434.54,4430.71 U8.3@434.54,4413.27
NetR44_2: R44.2 Y1.1 | length 182.4
  Layer 1 - Top Layer w10: Y1.1@361.07,1900.87 361.07,1907.56 409.38,1955.87 479.38,1955.87 v1(494.38,1940.87)
  Layer 6 - Bottom Layer w10: R44.2@478.2,1940.87 v1(494.38,1940.87)
NetR45_1: R45.1 R46.2 Y1.3 | length 163.4
  Layer 1 - Top Layer w8: v1(402,1849) 402,1848.25 448.53,1801.72 Y1.3@447.69,1800.87 462.69,1785.87 R46.2@505.76,1785.87
  Layer 6 - Bottom Layer w8: R45.1@370.62,1849 v1(402,1849)
NetR46_1: R46.1 U1.5 | length 134.9
  Layer 1 - Top Layer w8: R46.1@553,1785.87 578.44,1785.87 580.32,1787.74 581.25,1787.74 592.38,1798.87 658.82,1798.87 U1.5@675.61,1782.08
NetR49_1: R49.1 R51.2 U1.3 | length 283.6
  Layer 1 - Top Layer w8: v1(544.38,1835.87) 559.38,1835.87 564.38,1830.87 682.49,1830.87 U1.3@703.45,1809.92
  Layer 6 - Bottom Layer w8: v1(544.38,1835.87) 593,1835.87 R49.1@599.38,1842.25 626,1842.25 640.76,1827.49 640.76,1825.87 R51.2@645.76,1820.87
NetR52_1: R52.1 U1.6 | length 107
  Layer 1 - Top Layer w8: v1(609.38,1775.87) 624.38,1775.87 630.38,1781.87 647.98,1781.87 U1.6@661.69,1768.16
  Layer 6 - Bottom Layer w8: R52.1@605.76,1730.87 609.38,1734.49 v1(609.38,1775.87)
NetR54_2: R54.2 U1.4 | length 335.8
  Layer 1 - Top Layer w8: v1(514.38,1820.87) 524.38,1820.87 530.25,1815 670.53,1815 U1.4@689.53,1796
  Layer 6 - Bottom Layer w8: v1(514.38,1820.87) 534.38,1800.87 621.38,1800.87 645.76,1776.49 R54.2@645.76,1775.87
NetR64_2: R64.2 U10.27 U10.28 | length 62.5
  Layer 6 - Bottom Layer w30: v4(521,4910) R64.2@583.5,4910
NetR66_2: R66.2 U10.25 U10.26 | length 212.3
  Layer 6 - Bottom Layer w30: R66.2@417.5,4719 417.5,4858.5 v4(469,4910)
NetR71_2: R71.2 U10.11 | length 73.7
  Layer 1 - Top Layer w10: U10.11@276.43,5193.14 276.43,5235.43 284.62,5243.62 R71.2@284.62,5263.49
NetR78_2: R78.2 U10.17 U10.18 | length 59.2
  Layer 1 - Top Layer w30: v4(265,4907) 265,4870 276.29,4858.71 R78.2@276.29,4852.5
NetR80_2: R80.2 U10.15 U10.16 | length 54.3
  Layer 1 - Top Layer w30: R80.2@211,4852.68 v4(211,4907)
NetR97_2: R97.2 U12.11 | length 145.2
  Layer 1 - Top Layer w10: v1(1184.97,2941.93) U12.11@1184.97,3006.26
  Layer 6 - Bottom Layer w10: R97.2@1159.38,3012.25 1159.38,3005.87 1184.97,2980.28 v1(1184.97,2941.93)
NetR98_2: R98.2 U12.12 | length 99.3
  Layer 1 - Top Layer w10: v1(1210.56,2960.87) U12.12@1210.56,3006.26
  Layer 6 - Bottom Layer w10: R98.2@1204.38,3012.25 1204.38,2985.87 1210.56,2979.69 v1(1210.56,2960.87)
NetR99_2: R99.2 U12.13 | length 140.1
  Layer 1 - Top Layer w10: v1(1236.15,2941.93) U12.13@1236.15,3006.26
  Layer 6 - Bottom Layer w10: v1(1236.15,2941.93) 1236.15,2977.64 1249.38,2990.87 R99.2@1249.38,3012.25
NetR100_2: R100.2 U12.14 | length 110.3
  Layer 1 - Top Layer w10: v1(1261.74,2960.87) U12.14@1261.74,3006.26
  Layer 6 - Bottom Layer w10: v1(1261.74,2960.87) 1274.38,2973.51 1274.38,2990.87 1294.38,3010.87 R100.2@1294.38,3012.25
NetR101_2: R101.2 U12.25 | length 120.5
  Layer 1 - Top Layer w10: R101.2@1228.62,3412.25 1228.62,3406.63 1261.74,3373.51 U12.25@1261.74,3305.48
NetR102_2: R102.2 U12.26 | length 146.1
  Layer 1 - Top Layer w10: R102.2@1183.62,3412.25 1183.62,3386.63 1194.38,3375.87 1224.38,3375.87 1236.15,3364.1 U12.26@1236.15,3305.48
NRESET_SOC: J18.14 U12.31 | length 4820.5
  Layer 1 - Top Layer w10: v1(1108.2,3260.08) U12.31@1108.2,3305.48
  Layer 3 - Sensitive w10: v1(202,1414) 202,1904 637,2339 637,2649 542,2744 542,2864 487,2919 431.25,2919 399.38,2950.87 399.38,3490.87 385,3505.25 385,3591.49 434.38,3640.87 474.38,3640.87 v1(494.38,3660.87) ; v1(1084.38,3520.87) 1084.38,3283.9 v1(1108.2,3260.08)
  Layer 6 - Bottom Layer w10: v1(202,1414) 202,1224 312,1114 312,964 776.95,499.05 J18.14@776.95,428.52 ; v1(494.38,3660.87) 524.38,3660.87 584.38,3600.87 1004.38,3600.87 v1(1084.38,3520.87)
PDB_UB960: R49.2 U12.17 | length 1849.7
  Layer 1 - Top Layer w8: v1(1039.38,2434) 1039.38,2535.87 1094.38,2590.87 v1(1094.38,2695.87)
  Layer 1 - Top Layer w10: U12.17@1338.51,3006.26 v1(1338.51,3051.66)
  Layer 3 - Sensitive w10: v1(1094.38,2695.87) 1049.38,2740.87 1049.38,2820.87 1064.38,2835.87 1154.38,2835.87 1204.38,2885.87 1304.38,2885.87 1338.51,2920 v1(1338.51,3051.66)
  Layer 6 - Bottom Layer w8: R49.2@599.38,1893.87 R49.2@599.38,1889.49 637,1927.11 637,2069 662,2094 662,2369 702,2409 1014.38,2409 v1(1039.38,2434)
PG_1V1: J10.3 R39.2 U8.8 U9.2 | length 1527.7
  Layer 1 - Top Layer w10: U8.8@474.38,4338.47 v1(491.98,4338.47)
  Layer 3 - Sensitive w10: v1(219.38,4095.87) 259.38,4135.87 259.38,4210.87 294.38,4245.87 334.38,4245.87 426.98,4338.47 v1(491.98,4338.47)
  Layer 6 - Bottom Layer w10: U9.2@219.38,4051.58 v1(219.38,4095.87) ; v1(491.98,4338.47) R39.2@538.28,4338.47 ; R39.2@538.65,4340.87 538.65,4306.6 599.38,4245.87 599.38,4125.87 624.38,4100.87 834.38,4100.87 874.38,4060.87 874.38,4005.87 894.38,3985.87 989.38,3985.87 1139.38,3835.87 J10.3@1209.38,3835.87
PG_1V8: J10.2 R34.2 U6.8 U7.2 | length 1575.7
  Layer 1 - Top Layer w10: U6.8@738.38,4333.47 v1(755.98,4333.47)
  Layer 3 - Sensitive w10: v1(219.38,4245.87) 239.38,4265.87 324.38,4265.87 394.38,4335.87 394.38,4410.87 424.38,4440.87 519.38,4440.87 539.38,4420.87 539.38,4350.87 556.78,4333.47 v1(755.98,4333.47)
  Layer 6 - Bottom Layer w10: U7.2@219.38,4201.58 v1(219.38,4245.87) ; v1(755.98,4333.47) 755.98,4291.01 R34.2@761.12,4285.87 761.12,4254.13 769.38,4245.87 849.38,4245.87 869.38,4225.87 869.38,4125.87 894.38,4100.87 1124.38,4100.87 1154.38,4070.87 1154.38,3990.87 J10.2@1209.38,3935.87
PG_3V3: J10.1 R29.1 R103.2 U4.8 U5.2 | length 4227.7
  Layer 1 - Top Layer w10: U4.8@1019.38,4333.47 v1(1036.98,4333.47)
  Layer 3 - Sensitive w10: v1(219.38,4395.87) 219.38,4445.62 136,4529 136,4558 80,4614 80,5096.49 139.38,5155.87 139.38,5285.87 184.38,5330.87 579.38,5330.87 654.38,5255.87 654.38,5080.87 749.38,4985.87 749.38,4645.87 919.38,4475.87 919.38,4355.87 941.78,4333.47 v1(1036.98,4333.47)
  Layer 6 - Bottom Layer w10: U5.2@219.38,4351.58 v1(219.38,4395.87) ; v1(1036.98,4333.47) 1036.98,4291.97 R29.1@1030.88,4285.87 1074.38,4285.87 1209.38,4150.87 J10.1@1209.38,4035.87 1254.38,4035.87 1274.38,4015.87 1274.38,3475.87 1134.38,3335.87 1134.38,3245.87 1079.38,3190.87 R103.2@1079.38,3077.36
RIN0_N: C11.2 U1.51 | length 2570.5
  Layer 1 - Top Layer w7: U1.51@948.45,1656.78 v3(964.44,1672.77) ; v3(1989.62,1321.13) 1996.09,1327.6 cw(c2004.62,1319.06) 2004.62,1331.13 C11.2@2021,1331.13
  Layer 3 - Sensitive w5: v3(964.44,1672.77) ccw(c964.44,1689.3) 976.12,1677.6 1135.3,1836.78 cw(c1213.08,1759) 1213.08,1869 1260.58,1869 cw(c1260.58,1759) 1338.36,1836.78 1399.78,1775.36 cw(c1322,1697.58) 1432,1697.58 1432,1139 ccw(c1532,1139) 1461.29,1068.29 1467,1062.58 ccw(c1515.28,1110.86) 1515.28,1042.58 1556.64,1042.58 ccw(c1556.64,1127.93) 1617,1067.58 1617.71,1068.29 ccw(c1547,1139) 1647,1139 1647,1532.79 cw(c1708.21,1532.79) 1664.93,1576.07 1665.18,1576.32 cw(c1732,1509.5) 1732,1604 1751.64,1604 cw(c1751.64,1508.64) 1819.07,1576.07 cw(c1751.64,1508.64) 1847,1508.64 1847,1387.28 ccw(c1915.28,1387.28) 1867,1339 ccw(c1928.25,1400.25) 1928.25,1313.63 1982.12,1313.63 ccw(c1982.12,1321.13) v3(1989.62,1321.13)
RIN0_P: C9.2 U1.50 | length 2571.9
  Layer 1 - Top Layer w7: U1.50@962.37,1642.86 v3(978.35,1658.85) ; v3(1989.62,1296.13) 1989.62,1291.38 ccw(c2002,1291.38) 2002,1279 C9.2@2022,1279
  Layer 3 - Sensitive w5: v3(978.35,1658.85) cw(c994.89,1658.85) 983.2,1670.54 1142.37,1829.71 cw(c1213.08,1759) 1213.08,1859 1260.58,1859 cw(c1260.58,1759) 1331.29,1829.71 1392.71,1768.29 cw(c1322,1697.58) 1422,1697.58 1422,1139 ccw(c1532,1139) 1454.22,1061.22 1459.93,1055.51 ccw(c1515.28,1110.86) 1515.28,1032.58 1556.64,1032.58 ccw(c1556.64,1127.93) 1624.07,1060.51 1624.78,1061.22 ccw(c1547,1139) 1657,1139 1657,1532.79 cw(c1708.21,1532.79) 1672,1569 1672.25,1569.25 cw(c1732,1509.5) 1732,1594 1751.64,1594 cw(c1751.64,1508.64) 1812,1569 cw(c1751.64,1508.64) 1837,1508.64 1837,1387.28 ccw(c1915.28,1387.28) 1859.93,1331.93 ccw(c1928.25,1400.25) 1928.25,1303.63 1982.12,1303.63 cw(c1982.12,1296.13) v3(1989.62,1296.13)
RIN1_N: C12.2 U1.54 | length 2570.9
  Layer 1 - Top Layer w7: U1.54@906.68,1698.55 v3(922.67,1714.53) ; v3(1992.18,2160.13) 1998.64,2166.6 cw(c2007.18,2158.06) 2007.18,2170.13 C12.2@2023.56,2170.13
  Layer 3 - Sensitive w5: v3(922.67,1714.53) ccw(c922.67,1731.07) 934.35,1719.37 945.49,1730.51 ccw(c893.56,1782.44) 967,1782.44 967,1982.58 cw(c1077,1982.58) 999.22,2060.36 1295.64,2356.78 cw(c1373.42,2279) 1373.42,2389 1445.58,2389 cw(c1445.58,2279) 1523.36,2356.78 1529.78,2350.36 cw(c1452,2272.58) 1562,2272.58 1562,2240.42 cw(c1452,2240.42) 1529.78,2162.64 1431.29,2064.15 ccw(c1502,1993.44) 1402,1993.44 1402,1979 ccw(c1486.5,1979) 1426.75,1919.25 1562.71,1783.29 ccw(c1633.42,1854) 1633.42,1754 1745.58,1754 ccw(c1745.58,1850.42) 1842,1850.42 1842,2099.86 cw(c1886.14,2099.86) 1854.93,2131.07 cw(c1910.28,2075.72) 1910.28,2154 1977.38,2154 ccw(c1977.38,2174.93) v3(1992.18,2160.13)
RIN1_P: C10.2 U1.53 | length 2572.3
  Layer 1 - Top Layer w7: U1.53@920.6,1684.63 v3(936.59,1700.62) ; v3(1992.18,2137.87) 1992.18,2133.12 ccw(c2004.56,2133.12) 2004.56,2120.74 C10.2@2024.56,2120.74
  Layer 3 - Sensitive w5: v3(936.59,1700.62) cw(c953.12,1700.62) 941.43,1712.31 952.56,1723.44 ccw(c893.56,1782.44) 977,1782.44 977,1982.58 cw(c1077,1982.58) 1006.29,2053.29 1302.71,2349.71 cw(c1373.42,2279) 1373.42,2379 1445.58,2379 cw(c1445.58,2279) 1516.29,2349.71 1522.71,2343.29 cw(c1452,2272.58) 1552,2272.58 1552,2240.42 cw(c1452,2240.42) 1522.71,2169.71 1424.22,2071.22 ccw(c1502,1993.44) 1392,1993.44 1392,1979 ccw(c1486.5,1979) 1419.68,1912.18 1555.64,1776.22 ccw(c1633.42,1854) 1633.42,1744 1745.58,1744 ccw(c1745.58,1850.42) 1852,1850.42 1852,2099.86 cw(c1886.14,2099.86) 1862,2124 cw(c1910.28,2075.72) 1910.28,2144 1977.38,2144 cw(c1977.38,2123.07) v3(1992.18,2137.87)
RIN2_N: C25.2 U1.60 | length 2572.6
  Layer 1 - Top Layer w7: U1.60@823.14,1782.09 v3(839.13,1798.07) ; v3(1993.38,3004.87) 1999.84,3011.33 cw(c2008.38,3002.8) 2008.38,3014.87 C25.2@2024.76,3014.87
  Layer 3 - Sensitive w5: v3(839.13,1798.07) ccw(c839.13,1814.61) 850.81,1802.91 ccw(c816.56,1837.16) 865,1837.16 865,1851 ccw(c845.69,1851) 859.34,1864.66 857,1867 cw(c881.14,1891.14) 847,1891.14 847,2019 cw(c881.14,2019) 856.99,2043.13 1435.64,2621.78 cw(c1513.42,2544) 1513.42,2654 1537,2654 cw(c1537,2571.57) 1595.28,2629.86 1614.07,2611.07 cw(c1558.72,2555.72) 1637,2555.72 1637,2485.42 ccw(c1688.72,2485.42) 1652.15,2448.85 1662,2439 ccw(c1710.28,2487.28) 1710.28,2419 1860.58,2419 ccw(c1860.58,2495.42) 1937,2495.42 1937,2632.58 ccw(c1837,2632.58) 1907.71,2703.29 1824.22,2786.78 cw(c1902,2864.56) 1792,2864.56 1792,2915.72 cw(c1870.28,2915.72) 1814.93,2971.07 cw(c1878.42,2907.58) 1878.42,2997.37 1975.27,2997.37 ccw(c1975.27,3022.98) v3(1993.38,3004.87)
RIN2_P: C23.2 U1.59 | length 2574
  Layer 1 - Top Layer w7: U1.59@837.06,1768.17 v3(853.05,1784.15) ; v3(1993.38,2979.87) 1993.38,2975.12 ccw(c2005.76,2975.12) 2005.76,2962.74 C23.2@2025.76,2962.74
  Layer 3 - Sensitive w5: v3(853.05,1784.15) cw(c869.58,1784.15) 857.89,1795.84 ccw(c816.59,1837.15) 875,1837.15 875,1851 ccw(c845.69,1851) 866.41,1871.73 864.07,1874.07 cw(c881.14,1891.14) 857,1891.14 857,2019 cw(c881.14,2019) 864.07,2036.07 1442.71,2614.71 cw(c1513.42,2544) 1513.42,2644 1537,2644 cw(c1537,2571.57) 1588.21,2622.79 1607,2604 cw(c1558.72,2555.72) 1627,2555.72 1627,2485.42 ccw(c1688.72,2485.42) 1645.08,2441.78 1654.93,2431.93 ccw(c1710.28,2487.28) 1710.28,2409 1860.58,2409 ccw(c1860.58,2495.42) 1947,2495.42 1947,2632.58 ccw(c1837,2632.58) 1914.78,2710.36 1831.29,2793.85 cw(c1902,2864.56) 1802,2864.56 1802,2915.72 cw(c1870.28,2915.72) 1822,2964 cw(c1878.42,2907.58) 1878.42,2987.37 1975.27,2987.37 cw(c1975.27,2961.76) v3(1993.38,2979.87)
RIN3_N: C26.2 U1.63 | length 2571.1
  Layer 1 - Top Layer w7: U1.63@781.37,1823.86 v3(797.36,1839.84) ; v3(1993.38,3826.87) 1999.84,3833.33 cw(c2008.38,3824.8) 2008.38,3836.87 C26.2@2024.76,3836.87
  Layer 3 - Sensitive w5: v3(797.36,1839.84) ccw(c797.36,1856.38) 809.04,1844.68 ccw(c794.65,1859.07) 815,1859.07 815,2074.72 cw(c915,2074.72) 844.29,2145.43 1817.71,3118.85 ccw(c1747,3189.56) 1847,3189.56 1847,3725.72 cw(c1925.28,3725.72) 1869.93,3781.07 1882.43,3793.57 cw(c1943.82,3732.18) 1943.82,3819 1974.38,3819 ccw(c1974.38,3845.87) v3(1993.38,3826.87)
RIN3_P: C24.2 U1.62 | length 2571.6
  Layer 1 - Top Layer w7: U1.62@795.29,1809.94 v3(811.28,1825.93) ; v3(1993.38,3801.13) 1993.38,3796.38 ccw(c2005.76,3796.38) 2005.76,3784 C24.2@2025.76,3784
  Layer 3 - Sensitive w5: v3(811.28,1825.93) cw(c827.81,1825.93) 816.12,1837.62 ccw(c794.68,1859.06) 825,1859.06 825,2066.44 cw(c935,2066.44) 857.22,2144.22 1824.78,3111.78 ccw(c1747,3189.56) 1857,3189.56 1857,3725.72 cw(c1925.28,3725.72) 1877,3774 1889.5,3786.5 cw(c1943.82,3732.18) 1943.82,3809 1974.38,3809 cw(c1974.38,3782.13) v3(1993.38,3801.13)
SBWTCK1: J31.4 U12.1 | length 2738.4
  Layer 1 - Top Layer w10: U12.1@929.06,3006.26 929.06,3055.55 934.38,3060.87 934.38,3100.87 959.38,3125.87 v1(1104.38,3125.87)
  Layer 6 - Bottom Layer w10: v1(1104.38,3125.87) 1104.38,3190.87 1154.38,3240.87 1154.38,3325.87 1294.38,3465.87 1294.38,3945.87 1314.38,3965.87 1414.38,3965.87 1585,4136.49 1585,4311 1948,4674 2078,4674 2284.87,4880.87 J31.4@2367.38,4880.87
SEH: U10.7 U12.22 | length 2818.4
  Layer 1 - Top Layer w10: U10.7@378.8,5193.14 378.8,5287.8 445,5354 v1(553,5354) ; v1(1338.51,3260.08) U12.22@1338.51,3305.48
  Layer 3 - Sensitive w10: v1(553,5354) 651,5354 720,5285 720,5053 860,4913 860,4768 1265,4363 1265,3423 1338.51,3349.49 v1(1338.51,3260.08)
SEL: U10.8 U12.21 | length 3055.8
  Layer 1 - Top Layer w10: U10.8@354,5178 354,5325 408,5379 v1(538,5379) ; v1(1364.1,3241.14) U12.21@1364.1,3305.48
  Layer 3 - Sensitive w10: v1@541,5379 690,5379 754,5315 754,5135 914,4975 1037,4975 1069,4943 1069,4593 1288,4374 1288,3431 1364.1,3354.9 v1(1364.1,3241.14)
SENSE_CAM: R74.2 U10.10 U12.20 | length 3397
  Layer 1 - Top Layer w10: R74.2@191.62,5386 242,5386 313,5315 313,5237 302.02,5226.02 U10.10@302.02,5193.14 ; R74.2@196.38,5387.24 v1(196.38,5435.87) ; v1(1389.69,3260.08) U12.20@1389.69,3305.48
  Layer 3 - Sensitive w10: v1(196.38,5435.87) 687.13,5435.87 775,5348 775,5148.74 927.87,4995.87 1044.38,4995.87 1089.38,4950.87 1089.38,4600.87 1309.38,4380.87 1309.38,3435.87 1389.69,3355.55 v1(1389.69,3260.08)
SPI_MISO_0: J20.5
